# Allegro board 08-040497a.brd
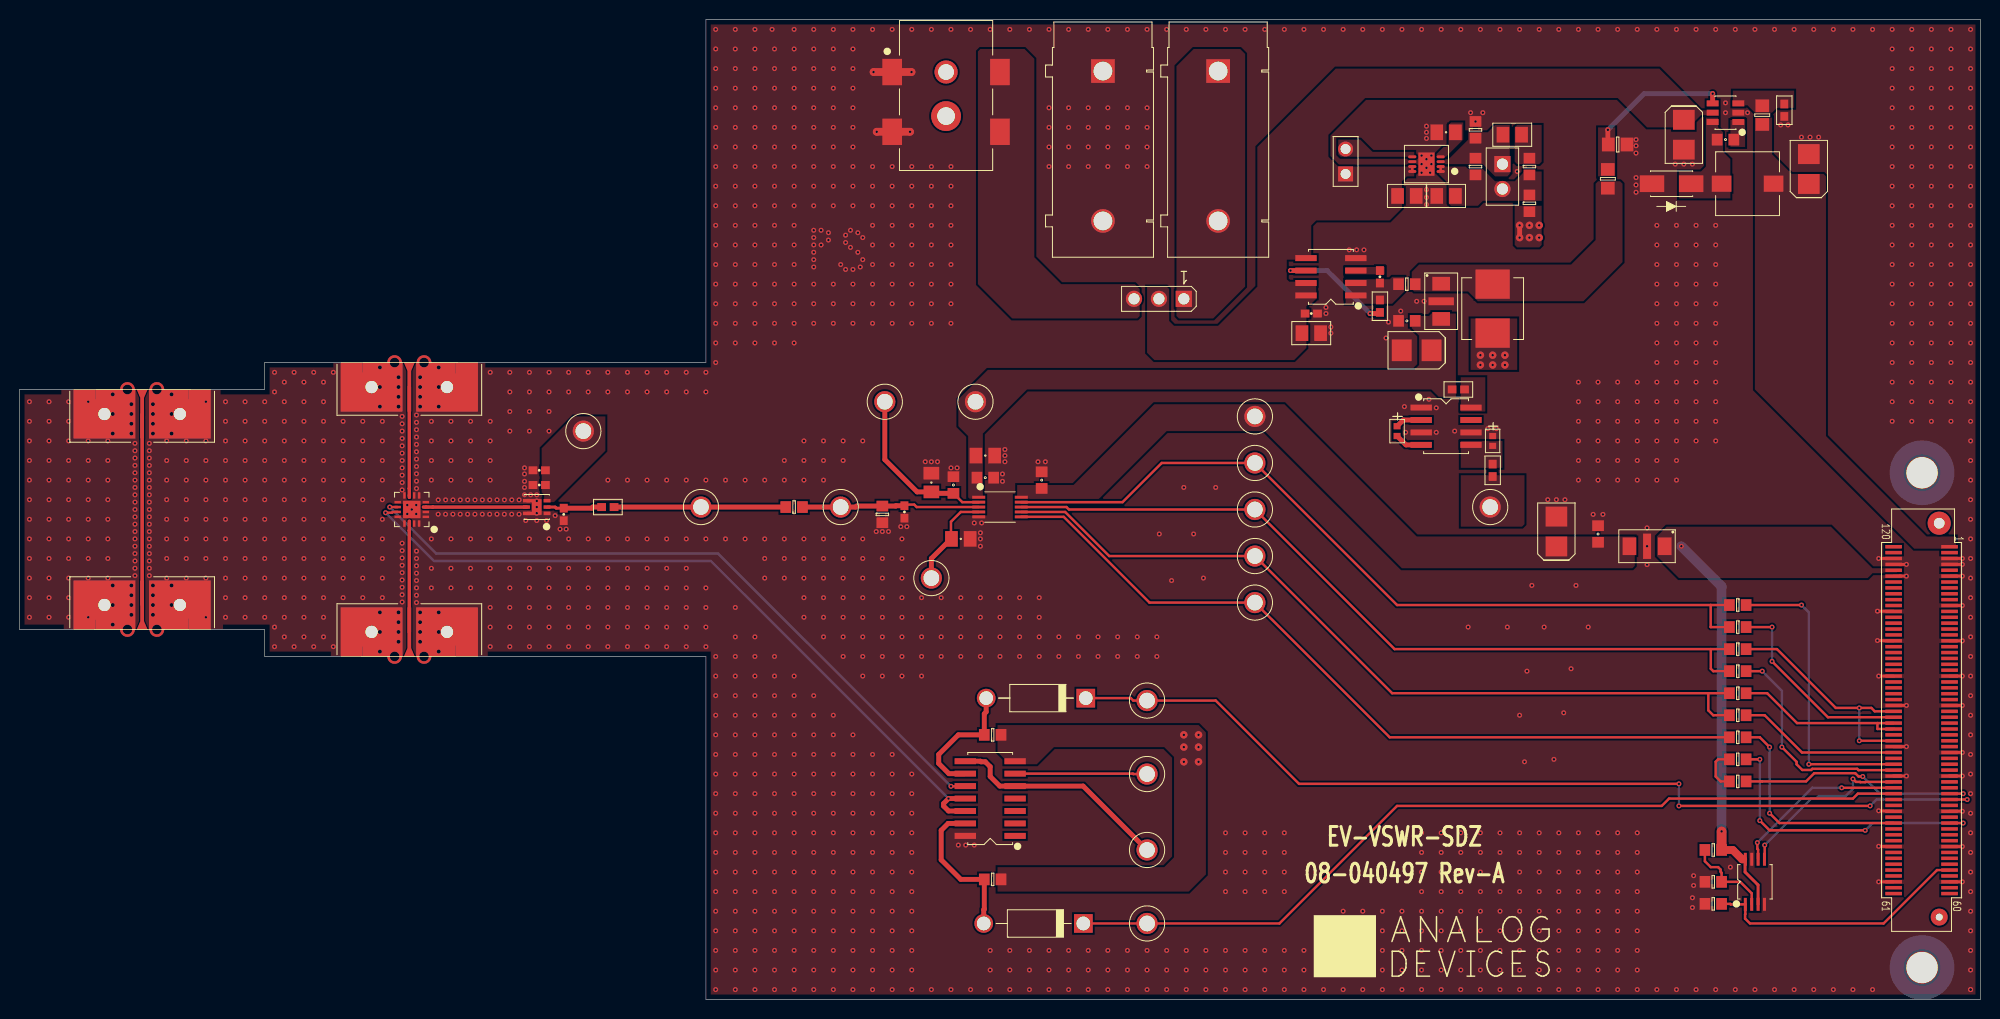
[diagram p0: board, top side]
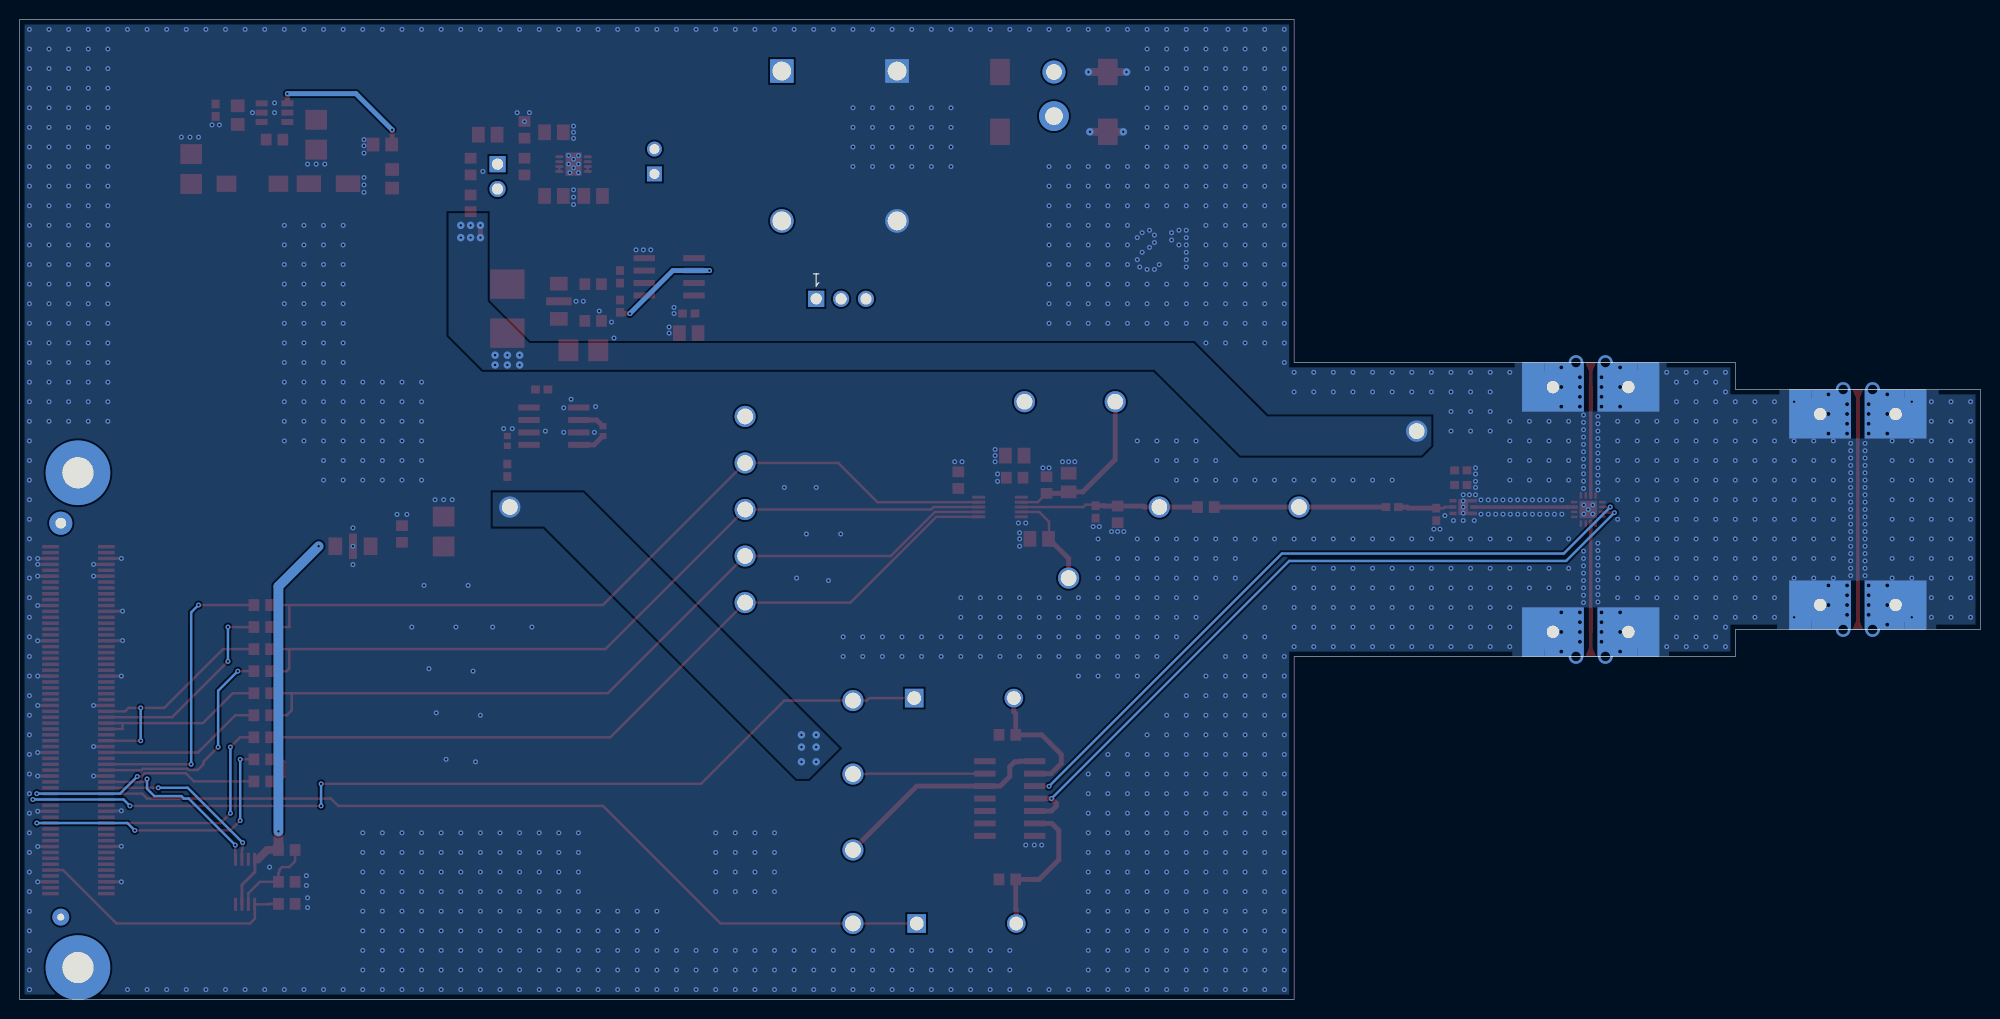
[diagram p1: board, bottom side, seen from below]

Outline 200 x 100 mm; copper layers: TOP, L2-GND, L3-GND, BOTTOM. Coordinates in mm from the lower left corner of the outline.
Outline path: 0,62.25 0,37.75 25,37.75 25,35 70,35 70,0 200,0 200,100 70,100 70,65 25,65 25,62.25 0,62.25

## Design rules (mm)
nets with their own width: min track width 0.3; nets AGND

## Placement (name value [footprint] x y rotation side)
A  WHT  [CNLOOPTP]  115 15.25 0 top
B  WHT  [CNLOOPTP]  115 23 0 top
C1  100pF  [C0402]  53 54 180 top
C2  0.1UF  [C0402]  53 52.5 180 top
C3  TBD0402  [C0402]  55.5 49.5 270 top
C9  1uF  [C0805]  98.5 55.5 0 top
C10  0.1uF  [C0603]  98.5 53.25 0 top
C11  0.1uF  [C0603]  95.25 52.5 90 top
C12  1uF  [C0805]  93 52.75 90 top
C14  1uF  [C0805]  96 47 0 top
C15  0.1uF  [C0603]  104.25 53 90 top
C17  0.01uF  [C0402]  131.75 70 0 top
C18  0.01UF  [C0402]  138.75 73.75 270 top
C19  0.1uF  [C0603]  141.5 69.25 180 top
C20  10uF  [C3528]  142.5 66.25 180 top
C21  10uF  [C3528]  169.75 88.25 270 top
C22  0.1uF  [C0603]  174 87.75 180 top
C23  10uF  [C3528]  182.5 84.75 90 top
C24  0.1uF  [C0603]  161 47.5 90 top
C25  10uF  [C3528]  156.75 47.75 90 top
C26  1UF  [C0805H53]  131.75 68 0 top
C29  1UF  [C0805H53]  152.25 88.25 0 top
C30  4.7UF  [C0805H53]  145.5 82 0 top
C31  1000pF  [C0805]  145.5 88.5 0 top
C32  4.7UF  [C0805H53]  141.5 82 180 top
C35  10uF  [CPL0402]  150.25 57 270 top
C36  10uF  [CPL0402]  140.5 58 270 top
C37  TBD0402  [C0402]  90.25 49.75 270 top
D1  B230A-13-F  [SMA-2]  168.5 83.25 180 top
D2  1N4733A  [DO41]  108.5 7.75 180 top
D3  1N4733A  [DO41]  108.75 30.75 180 top
GND  571-0100  [CNDELTRON-571]  110.5 94.75 270 top
GPIO1  WHT  [CNLOOPTP]  115 7.75 0 top
GPIO2  WHT  [CNLOOPTP]  115 30.5 0 top
J3  02K243-40M  [CNROS02K243-40M]  12.5 37.75 270 top
J4  FX8-120S-SV(21)  [CNHRSFX8-120S-SV_A]  194 28.5 270 top
J5  02K243-40M  [CNROS02K243-40M]  12.5 62.25 90 top
L1  6.8uH  [LSMSQ236H79_B]  176.25 83.25 0 top
L2  33uH  [L2525]  150.25 70.5 90 top
LC1  1000pF  [FLSML126W71H87]  145 71.25 270 top
LC2  1000pF  [FLSML126W71H87]  166 46.25 180 top
LK6  SAMTECTSW10608GS3PIN  [CNBERG1X3H205LD36]  118.75 71.5 180 top
LK21  M20-9990245  [CNHARWIN-M20-9990246]  151.25 85.25 270 top
LK22  69157-102  [CNBERG69157-102]  135.25 84.25 90 top
NOREF  -  []  0 37.75 90 top
NOREF#2  -  []  -153.6 -177.4 0 top
NOREF#3  -  []  245.81 331.87 0 top
NOREF#4  -  []  -153.6 -177.4 0 top
NOREF#5  -  []  200 0 90 top
NOREF#6  -  []  44.07 50.74 0 top
NOREF#7  -  []  0 62.25 0 top
NOREF#8  -  []  -133.3 -28.65 0 top
NOREF#9  -  []  -153.6 -177.4 0 top
NOREF#10  -  []  129.5 140.25 0 top
NOREF#11  -  []  40.89 52.79 0 top
NOREF#12  -  []  25 65 0 top
NOREF#13  -  []  40.54 48.23 0 top
NOREF#14  -  []  38.12 33.5 0 top
NOREF#15  -  []  70 100 0 top
NOREF#16  -  []  25 62.25 90 top
NOREF#17  -  []  41.3 51.3 0 top
NOREF#18  -  []  70 0 90 top
NOREF#19  -  []  39.11 52.78 0 top
NOREF#20  -  []  261.5 -98 0 top
NOREF#21  -  []  44.08 49.26 0 top
NOREF#22  -  []  25 35 90 top
NOREF#23  -  []  70 65 90 top
NOREF#24  -  []  132 2.25 180 bottom
R1  0  [R0402]  60 50.25 0 top
R12  330K  [R0402]  138.75 70.75 90 top
R13  3K  [R0805]  162 83.75 90 top
R14  1.5K  [R0805]  163 87.25 0 top
R15  53.6K  [R0805]  177.75 90.25 90 top
R16  10.2K  [R0402]  180 90.75 270 top
R17  TBD0603  [R0603]  175.25 33.5 180 top
R18  TBD0603  [R0603]  175.25 40.25 180 top
R19  TBD0603  [R0603]  175.25 29 180 top
R20  0  [R0603]  175.25 35.75 180 top
R21  0  [R0603]  175.25 31.25 180 top
R22  0  [R0603]  175.25 38 180 top
R23  0  [R0603]  175.25 24.5 0 top
R24  TBD0603  [R0603]  175.25 22.25 0 top
R25  TBD0603  [R0603]  175.25 26.75 180 top
R26  TBD0603  [R0603]  172.75 15.25 180 top
R27  100K  [R0603]  172.75 12 180 top
R28  100K  [R0603]  172.75 9.75 180 top
R30  10K  [R0603]  99.25 12.25 0 top
R31  200  [R0603]  79 50.25 0 top
R32  0  [R0603]  154 81.25 270 top
R33  3K  [R0603]  154 85 270 top
R34  120K  [R0603]  148.5 85 270 top
R35  39K  [R0603]  148.5 88.75 270 top
R36  10K  [R0603]  99.25 27 0 top
R37  0  [R0402]  146.75 62.25 180 top
R38  0  [R0402]  150.25 54 270 top
R39  0  [R0603]  141.5 73 0 top
R40  340  [R0603]  88 49.5 270 top
RF1  02K243-40M  [CNROS02K243-40M]  39.75 65 90 top
RF2  02K243-40M  [CNROS02K243-40M]  39.75 35 270 top
T1  WHT  [CNLOOPTP]  97.5 61 0 top
T2  WHT  [CNLOOPTP]  88.25 61 0 top
T3  WHT  [CNLOOPTP]  83.75 50.25 0 top
T4  WHT  [CNLOOPTP]  93 43 0 top
T6  WHT  [CNLOOPTP]  126 40.5 0 top
T7  WHT  [CNLOOPTP]  126 45.25 0 top
T8  WHT  [CNLOOPTP]  126 50 0 top
T9  WHT  [CNLOOPTP]  126 54.75 0 top
T10  WHT  [CNLOOPTP]  126 59.5 0 top
U1  ADL6010ACPZN  [UQFN6_2_05X2_05_PAD1_6X1_A]  52.75 50.25 90 top
U2  AD7091RBRMZ  [RM10]  100 50.25 270 top
U5  24LC32A-I/MS  [MSOP8]  177 12 0 top
U6  ADP3303ARZ-5  [SO8]  133.75 73.75 90 top
U7  ADP2301AUJZ  [TSOT23_6]  174 90.5 90 top
U8  ADM7170ACPZ  [DFN8_3X3_PAD2_38X1_64]  143.5 85.25 90 top
U9  74LV04AD  [SO14]  99 20.5 90 top
U10  -  [HMC547LP3E]  40 50 90 top
U11  ADM660ARZ  [SO8]  145.5 58.5 270 top
V_OUT  WHT  [CNLOOPTP]  69.5 50.25 0 top
VDET  RED  [CNLOOPTP]  57.5 58 0 top
VNEG  WHT  [CNLOOPTP]  150 50.25 0 top
VSUPPLY  KLDX-SMT2-0202-ATR  [CNKYCONKLDX-SMT2-0202]  94.5 92.25 270 top
VSUPPLY_ALT  571-0500  [CNDELTRON-571]  122.25 94.75 270 top

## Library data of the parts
A B GPIO1 GPIO2 T1-T4 T6-T10 V_OUT VNEG = CNTP1P: User Part Number: UPN; alternate symbols: (CNBANANA_ALT); part number: CNTP1P_TH-WHT,E000946,CNLOOPTP
C1 = CAP: Tolerance: 5; User Part Number: UPN; part number: CAP_SM-100PF,50V,5,E007896,C0402; tolerance: 5
C2 = CAP: Tolerance: 10; User Part Number: UPN; part number: CAP_SM-0.1UF,16V,10,E007200,C0402; tolerance: 10
C3 C37 = CAP: User Part Number: UPN; part number: CAP_SM-TBD0402,TBD0402,TBD0402,E000381,C0402
C9 C12 C14 = CAP: Tolerance: 10; User Part Number: UPN; part number: CAP_SM-1UF,100V,10,E014208,C0805; tolerance: 10
C10 C11 = CAP: Tolerance: 10; User Part Number: UPN; part number: CAP_SM-0.1UF,50V,10,E011865,C0603; tolerance: 10
C15 C19 C22 C24 = CAP: Tolerance: 10; User Part Number: UPN; part number: CAP_SM-0.1UF,50V,10,E015248,C0603; tolerance: 10
C17 = CAP: Tolerance: -0.25; User Part Number: UPN; part number: CAP_SM-0.01UF,50V,-0.25,E012614,C0402; tolerance: -0.25
C18 = CAP: Tolerance: 10; User Part Number: UPN; part number: CAP_SM-0.01UF,25V,10,E010983,C0402; tolerance: 10
C20 C21 C23 C25 = CAPP: User Part Number: UPN; Tolerance: 10; part number: CAPP_SM-10UF,20V,10,E011346,C3528; tolerance: 10
C26 C29 = CAP: Tolerance: 10; User Part Number: UPN; part number: CAP_SM-1UF,50V,10,E007202,C0805H53; tolerance: 10
C30 C32 = CAP: Tolerance: 10; User Part Number: UPN; part number: CAP_SM-4.7UF,25V,10,E006908,C0805H53; tolerance: 10
C31 = CAP: Tolerance: 5; User Part Number: UPN; part number: CAP_SM-1000PF,50V,5,E010100,C0805; tolerance: 5
C35 C36 = CAPP: User Part Number: UPN; Tolerance: 20; part number: CAPP_SM-10UF,6.3V,20,E022099,CPL0402; tolerance: 20
D1 = DIOSCHOTTKY: User Part Number: UPN; Tolerance: N/A; alternate symbols: (SOD882L_ALT); part number: DIOSCHOTTKY_SM-B230A-13-F,30V,N/A,E012952,SMA-2; tolerance: N/A
D2 D3 = DIOZNR: Tolerance: 5; User Part Number: UPN; part number: DIOZNR_TH-1N4733A,5.1V,5,E001229,DO41; tolerance: 5
GND = CN2P: User Part Number: UPN; part number: CN2P_TH-571-0100,E007691,CNDELTRON-571
J3 J5 RF1 RF2 = CNBNC3P: User Part Number: UPN; alternate symbols: (CNROS32K243-40ML5_ALT); part number: CNBNC3P_SM-02K243-40M,E010821,CNROS02K243-40M
J4 = CN120P_V4: User Part Number: UPN; part number: CN120P_V4_SM-FX8-120S-SV(21),E016993,CNHRSFX8-120S-SV_A
L1 = IND: Tolerance: 30; User Part Number: UPN; alternate symbols: (L0402-2,L0603_ALT,L1008L_ALT); part number: IND_SM-6.8UH,30,E021189,LSMSQ236H79_B; tolerance: 30
L2 = IND: Tolerance: 20; User Part Number: UPN; alternate symbols: (L0402-2,L0603_ALT,L1008L_ALT); part number: IND_SM-33UH,20,E002425,L2525; tolerance: 20
LC1 LC2 = FLTR3P_V3: User Part Number: UPN; part number: FLTR3P_V3_SM-1000PF,E019686,FLSML126W71H87
LK6 = CN3P: User Part Number: UPN; part number: CN3P_TH-SAMTECTSW10608GS3PIN,E000812,CNBERG1X3H205LD36
LK21 = CNJMPRSHRT: User Part Number: UPN; part number: CNJMPRSHRT_TH-M20-9990245,E019487,CNHARWIN-M20-9990246
LK22 = CNJMPRSHRT: User Part Number: UPN; part number: CNJMPRSHRT_TH-69157-102,E000942,CNBERG69157-102
R1 R37 R38 = RES: Tolerance: 5; User Part Number: UPN; part number: RES_SM-0,E003438,1/16W,5,R0402; tolerance: 5
R12 = RES: Tolerance: 5; User Part Number: UPN; part number: RES_SM-330K,E003461,1/16W,5,R0402; tolerance: 5
R13 = RES: Tolerance: 0.1; User Part Number: UPN; part number: RES_SM-3K,E013665,1/4W,0.1,R0805; tolerance: 0.1
R14 = RES: Tolerance: 0.1; User Part Number: UPN; part number: RES_SM-1.5K,E003822,1/10W,0.1,R0805; tolerance: 0.1
R15 = RES: Tolerance: 1; User Part Number: UPN; part number: RES_SM-53.6K,E003980,1/8W,1,R0805; tolerance: 1
R16 = RES: Tolerance: 1; User Part Number: UPN; part number: RES_SM-10.2K,E019451,1/16W,1,R0402; tolerance: 1
R17-R19 R24-R26 = RES: User Part Number: UPN; part number: RES_SM-TBD0603,E004050,TBD0603,TBD0603,R0603
R20-R23 R32 R39 = RES: Tolerance: 1; User Part Number: UPN; part number: RES_SM-0,E004207,1/16W,1,R0603; tolerance: 1
R27 R28 = RES: Tolerance: 1; User Part Number: UPN; part number: RES_SM-100K,E018430,1/16W,1,R0603; tolerance: 1
R30 R36 = RES: Tolerance: 0.1; User Part Number: UPN; part number: RES_SM-10K,E003965,1/10W,0.1,R0603; tolerance: 0.1
R31 = RES: Tolerance: 0.1; User Part Number: UPN; part number: RES_SM-200,E003955,1/10W,0.1,R0603; tolerance: 0.1
R33 = RES: Tolerance: 5; User Part Number: UPN; part number: RES_SM-3K,E003850,1/10W,5,R0603; tolerance: 5
R34 = RES: Tolerance: 1; User Part Number: UPN; part number: RES_SM-120K,E007774,0.1W,1,R0603; tolerance: 1
R35 = RES: Tolerance: 1; User Part Number: UPN; part number: RES_SM-39K,E004234,1/16W,1,R0603; tolerance: 1
R40 = RES: Tolerance: 1; User Part Number: UPN; part number: RES_SM-340,E012541,1/10W,1,R0603; tolerance: 1
U1 = ADL6010: User Part Number: UPN; alternate symbols: (UQFN6_2_05X2_05_PAD1_6X1); part number: ADL6010_SM-ADL6010ACPZN,E019839,UQFN6_2_05X2_05_PAD1_6X1_A
U2 = AD7091R_V2: User Part Number: UPN; part number: AD7091R_V2_SM-AD7091RBRMZ,E015495,RM10
U5 = IC24FC256: User Part Number: UPN; part number: IC24FC256_SM-24LC32A-I/MS,E014160,MSOP8
U6 = ADP3303: User Part Number: UPN; part number: ADP3303_SM-ADP3303ARZ-5,E004966,SO8
U7 = ADP2301: User Part Number: UPN; part number: ADP2301_SM-ADP2301AUJZ,E007310,TSOT23_6
U8 = ADM7170: User Part Number: UPN; part number: ADM7170_SM-ADM7170ACPZ,E020662,DFN8_3X3_PAD2_38X1_64
U9 = 7404: User Part Number: UPN; part number: 7404_SM-74LV04AD,E002109,SO14
U10 = ICHMC547LP3E: User Part Number: UPN; part number: ICHMC547LP3E_SM-HMC547LP3E,E011702,HMC547LP3E
U11 = ADM660: User Part Number: UPN; part number: ADM660_TH-ADM660ARZ,E006022,SO8
VDET = CNTP1P: User Part Number: UPN; alternate symbols: (CNBANANA_ALT); part number: CNTP1P_TH-RED,E000947,CNLOOPTP
VSUPPLY = CN4P_V2: User Part Number: UPN; part number: CN4P_V2_SM-KLDX-SMT2-0202-ATR,E015303,CNKYCONKLDX-SMT2-0202
VSUPPLY_ALT = CN2P: User Part Number: UPN; part number: CN2P_TH-571-0500,E007692,CNDELTRON-571

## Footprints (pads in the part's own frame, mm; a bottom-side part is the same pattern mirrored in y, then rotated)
C0402
  rect 0.889x0.813 smd: 1(-0.635,0) 2(0.635,0)
C0603
  rect 1.092x1.194 smd: 1(-0.851,0) 2(0.851,0)
C0805
  rect 1.295x1.6 smd: 1(-0.953,0) 2(0.953,0)
C0805H53
  rect 1.295x1.6 smd: 1(-0.953,0) 2(0.953,0)
C3528
  rect 2.032x2.21 smd: N(1.524,0) P(-1.524,0)
CNBERG1X3H205LD36
  rect 1.651x1.651 hole 1.143: 1(0,0)
  round 1.651 hole 1.143: 2(2.54,0) 3(5.08,0)
CNBERG69157-102
  rect 1.524x1.524 hole 1.016: 1(0,0)
  round 1.524 hole 1.016: 2(2.54,0)
CNDELTRON-571
  rect 2.413x2.413 hole 1.905: 1(0,0)
  round 2.413 hole 1.905: 2(15.3,0)
CNHARWIN-M20-9990246
  rect 1.651x1.651 hole 1.143: 1(0,0)
  round 1.651 hole 1.143: 2(2.54,0)
CNHRSFX8-120S-SV_A
  round 3.302 hole 3.175 unplated: (-25.25,0.05) (25.25,0.05)
  round 2.362 hole 1.092 unplated: (-20.1,1.8)
  round 1.727 hole 0.711 unplated: (20.1,1.8)
  rect 0.356x1.702 smd: 1(-17.7,2.851) 2(-17.1,2.851) 3(-16.5,2.851) 4(-15.9,2.851) 5(-15.3,2.851) 6(-14.7,2.851) 7(-14.1,2.851) 8(-13.5,2.851) 9(-12.9,2.851) 10(-12.3,2.851) 11(-11.7,2.851) 12(-11.1,2.851) 13(-10.5,2.851) 14(-9.9,2.851) 15(-9.3,2.851) 16(-8.7,2.851) 17(-8.1,2.851) 18(-7.5,2.851) 19(-6.9,2.851) 20(-6.3,2.851) 21(-5.7,2.851) 22(-5.1,2.851) 23(-4.5,2.851) 24(-3.9,2.851) 25(-3.3,2.851) 26(-2.7,2.851) 27(-2.1,2.851) 28(-1.5,2.851) 29(-0.9,2.851) 30(-0.3,2.851) 31(0.3,2.851) 32(0.9,2.851) 33(1.5,2.851) 34(2.1,2.851) 35(2.7,2.851) 36(3.3,2.851) 37(3.9,2.851) 38(4.5,2.851) 39(5.1,2.851) 40(5.7,2.851) 41(6.3,2.851) 42(6.9,2.851) 43(7.5,2.851) 44(8.1,2.851) 45(8.7,2.851) 46(9.3,2.851) 47(9.9,2.851) 48(10.5,2.851) 49(11.1,2.851) 50(11.7,2.851) 51(12.3,2.851) 52(12.9,2.851) 53(13.5,2.851) 54(14.1,2.851) 55(14.7,2.851) 56(15.3,2.851) 57(15.9,2.851) 58(16.5,2.851) 59(17.1,2.851) 60(17.7,2.851) 61(17.7,-2.851) 62(17.1,-2.851) 63(16.5,-2.851) 64(15.9,-2.851) 65(15.3,-2.851) 66(14.7,-2.851) 67(14.1,-2.851) 68(13.5,-2.851) 69(12.9,-2.851) 70(12.3,-2.851) 71(11.7,-2.851) 72(11.1,-2.851) 73(10.5,-2.851) 74(9.9,-2.851) 75(9.3,-2.851) 76(8.7,-2.851) 77(8.1,-2.851) 78(7.5,-2.851) 79(6.9,-2.851) 80(6.3,-2.851) 81(5.7,-2.851) 82(5.1,-2.851) 83(4.5,-2.851) 84(3.9,-2.851) 85(3.3,-2.851) 86(2.7,-2.851) 87(2.1,-2.851) 88(1.5,-2.851) 89(0.9,-2.851) 90(0.3,-2.851) 91(-0.3,-2.851) 92(-0.9,-2.851) 93(-1.5,-2.851) 94(-2.1,-2.851) 95(-2.7,-2.851) 96(-3.3,-2.851) 97(-3.9,-2.851) 98(-4.5,-2.851) 99(-5.1,-2.851) 100(-5.7,-2.851) 101(-6.3,-2.851) 102(-6.9,-2.851) 103(-7.5,-2.851) 104(-8.1,-2.851) 105(-8.7,-2.851) 106(-9.3,-2.851) 107(-9.9,-2.851) 108(-10.5,-2.851) 109(-11.1,-2.851) 110(-11.7,-2.851) 111(-12.3,-2.851) 112(-12.9,-2.851) 113(-13.5,-2.851) 114(-14.1,-2.851) 115(-14.7,-2.851) 116(-15.3,-2.851) 117(-15.9,-2.851) 118(-16.5,-2.851) 119(-17.1,-2.851) 120(-17.7,-2.851)
CNKYCONKLDX-SMT2-0202
  round 2.362 hole 1.6 unplated: (-2.4,0)
  round 3.048 hole 1.803 unplated: (2.1,0)
  rect 2.692x2.007 smd: 1(-2.4,-5.497) 2(3.7,-5.497) 3(3.7,5.497) 4(-2.4,5.497)
CNLOOPTP
  round 2.159 hole 1.6: 1(0,0)
CNROS02K243-40M
  custom 0.275x0.275 smd: 1(-2.5,0)
  custom 1.251x1.251 hole 2.108: 2(-2.508,3.848) 3(-2.508,-3.848)
CPL0402
  rect 0.635x0.711 smd: N(0.5,0) P(-0.5,0)
DFN8_3X3_PAD2_38X1_64
  oval 0.305x0.838 smd: 1(-0.75,-1.45) 2(-0.25,-1.45) 3(0.25,-1.45) 4(0.75,-1.45) 5(0.75,1.45) 6(0.25,1.45) 7(-0.25,1.45) 8(-0.75,1.45)
  rect 2.388x1.651 smd: PAD(0,0)
DO41
  round 1.905 hole 1.397: A(10.16,0)
  rect 1.905x1.905 hole 1.397: C(0,0)
FLSML126W71H87
  rect 1.397x1.803 smd: 1(-1.799,0) 3(1.799,0)
  rect 0.813x2.591 smd: 2(0,0)
HMC547LP3E
  rect 0.254x0.66 smd: 1(-0.751,-1.435) 2(-0.25,-1.435) 3(0.25,-1.435) 4(0.751,-1.435) 9(0.751,1.435) 10(0.25,1.435) 11(-0.25,1.435) 12(-0.751,1.435)
  rect 0.66x0.254 smd: 5(1.435,-0.751) 6(1.435,-0.25) 7(1.435,0.25) 8(1.435,0.751) 13(-1.435,0.751) 14(-1.435,0.25) 15(-1.435,-0.25) 16(-1.435,-0.751)
  rect 1.778x1.778 smd: PAD(0,0)
L2525
  rect 2.997x3.505 smd: 1(-2.502,0) 2(2.502,0)
LSMSQ236H79_B
  rect 2.007x1.651 smd: 1(-2.65,0) 2(2.65,0)
MSOP8
  rect 0.305x1.321 smd: 1(-0.975,-2.3) 2(-0.325,-2.3) 3(0.325,-2.3) 4(0.975,-2.3) 5(0.975,2.3) 6(0.325,2.3) 7(-0.325,2.3) 8(-0.975,2.3)
R0402
  rect 0.889x0.813 smd: 1(-0.635,0) 2(0.635,0)
R0603
  rect 1.092x1.194 smd: 1(-0.851,0) 2(0.851,0)
R0805
  rect 1.295x1.397 smd: 1(-0.953,0) 2(0.953,0)
RM10
  rect 0.305x1.321 smd: 1(-1,-2.171) 2(-0.5,-2.171) 3(0,-2.171) 4(0.5,-2.171) 5(1,-2.171) 6(1,2.171) 7(0.5,2.171) 8(0,2.171) 9(-0.5,2.171) 10(-1,2.171)
SMA-2
  rect 2.489x1.702 smd: A(1.995,0) C(-1.995,0)
SO8
  rect 0.61x2.184 smd: 1(-1.905,-2.54) 2(-0.635,-2.54) 3(0.635,-2.54) 4(1.905,-2.54) 5(1.905,2.54) 6(0.635,2.54) 7(-0.635,2.54) 8(-1.905,2.54)
SO14
  rect 0.61x2.184 smd: 1(-3.81,-2.54) 2(-2.54,-2.54) 3(-1.27,-2.54) 4(0,-2.54) 5(1.27,-2.54) 6(2.54,-2.54) 7(3.81,-2.54) 8(3.81,2.54) 9(2.54,2.54) 10(1.27,2.54) 11(0,2.54) 12(-1.27,2.54) 13(-2.54,2.54) 14(-3.81,2.54)
TSOT23_6
  rect 0.61x1.219 smd: 1(-0.95,-1.31) 2(0,-1.31) 3(0.95,-1.31) 4(0.95,1.31) 5(0,1.31) 6(-0.95,1.31)
UQFN6_2_05X2_05_PAD1_6X1_A
  rect 0.356x0.711 smd: 1(-0.65,-1.05) 2(0,-1.05) 3(0.65,-1.05) 4(0.65,1.05) 5(0,1.05) 6(-0.65,1.05)
  rect 1.6x0.991 smd: PAD(0,0)

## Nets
AGND: C1.2(N2) C2.2(N2) C3.2(N2) C9.2(N2) C10.2(N2) C11.2(N2) C12.2(N2) C14.2(N2) C15.2(N2) C17.2(N2) C19.2(N2) C20.N(N2) C21.N(N2) C23.N(N2) C24.2(N2) C25.N(N2) C26.2(N2) C30.1(N1) C31.1(N1) C32.1(N1) C35.P(N1) C37.2(N2) D1.A(P) GND.1(N1) GND.2(N2) J3.2(SH1) J3.3(SH2) J4.3(GND1) J4.4(GND2) J4.6(GND3) J4.11(GND4) J4.17(GND5) J4.23(GND6) J4.28(GND7) J4.36(GND8) J4.40(GND9) J4.46(GND10) J4.52(GND11) J4.58(GND12) J4.63(GND13) J4.69(GND14) J4.75(GND15) J4.81(GND16) J4.86(GND17) J4.93(GND18) J4.98(GND19) J4.104(GND20) J4.109(GND21) J4.115(GND22) J4.117(GND23) J4.118(GND24) J5.2(SH1) J5.3(SH2) LC1.2(C) LC2.2(C) R14.2(N2) R16.2(N2) R27.2(N2) R28.2(N2) R35.1(N1) R40.2(N2) RF1.2(SH1) RF1.3(SH2) RF2.2(SH1) RF2.3(SH2) U1.1(GND1) U1.4(GND2) U1.6(GND3) U1.PAD U2.5(GND) U5.4(VSS) U5.7(WP) U6.4(GND) U7.2(GND) U8.6(GND) U8.PAD(EP) U9.14(VDD) U10.1(NC1) U10.2(GND1) U10.4(GND2) U10.5(NC2) U10.6(GND3) U10.8(GND4) U10.9(NC3) U10.12(NC4) U10.13(GND5) U10.15(GND6) U10.16(NC5) U10.PAD U11.1(FC) U11.3(GND) U11.6(LV) VSUPPLY.1(N1) VSUPPLY.2(N2)
AVDD: C9.1(N1) C10.1(N1) C19.1(N1) C20.P(N1) LC1.3(L2) R37.2(N2) T1.1(N1) U2.1(VDD)
A: A.1(N1) U9.5(IN) U9.8(OUT_N)
B: B.1(N1) U9.6(OUT_N)
CONVST: R23.1(N1) R24.1(N1)
CONVSTB: R25.2(N2) T6.1(N1) U2.6(CONVST_N)
CSB: R19.2(N2) R21.2(N2) T7.1(N1) U2.7(CS_N)
GPIO1: D2.C(N) GPIO1.1(N1) J4.78(GPIO1)
GPIO2: D3.C(N) GPIO2.1(N1) J4.44(GPIO2)
RF1: RF1.1(CNTR) U10.7(RF1)
RF2: RF2.1(CNTR) U10.14(RF2)
RF_TRUE_CAL: J3.1(CNTR) J5.1(CNTR)
RFIN: U1.5(RFIN) U10.3(RFC)
SCLK: R17.2(N2) R20.2(N2) T8.1(N1) U2.8(SCLK)
SDO: R18.2(N2) R22.2(N2) T9.1(N1) U2.9(SDO)
UNNAMED_3_AD7091RV2_I14_REFOUT: C11.1(N1) C12.1(N1) T2.1(N1) U2.2(REFOUT)
UNNAMED_3_AD7091RV2_I14_VIN: C37.1(N1) R31.2(N2) R40.1(N1) T3.1(N1) U2.3(VIN)
UNNAMED_3_CAP_I29_N1: C14.1(N1) T4.1(N1) U2.4(REGCAP)
UNNAMED_4_ADM660_I4_CAP: C36.N(N2) U11.4(CAP-)
UNNAMED_4_ADM660_I4_CAP_1: C36.P(N1) U11.2(CAP+)
UNNAMED_4_ADM660_I4_OUT: C35.N(N2) R38.1(N1) U11.5(OUT)
UNNAMED_4_ADM660_I4_V: R37.1(N1) U11.8(V+)
UNNAMED_4_ADM7170_I67_EN: LK22.2(S2) U8.5(EN)
UNNAMED_4_ADM7170_I67_SENSE: C29.1(N1) LK21.1(S1) R34.1(N1) R35.2(N2) U8.3(SENSE)
UNNAMED_4_ADM7170_I67_SS: C31.2(N2) U8.4(SS)
UNNAMED_4_ADM7170_I67_VOUT1: C30.2(N2) LK21.2(S2) R32.1(N1) R33.2(N2) R34.2(N2) U8.1(VOUT1) U8.2(VOUT2)
UNNAMED_4_ADP2301_I57_BST: C22.1(N1) U7.1(BST)
UNNAMED_4_ADP2301_I57_EN: R13.2(N2) R14.1(N1) U7.4(EN)
UNNAMED_4_ADP2301_I57_FB: R15.2(N2) R16.1(N1) U7.3(FB)
UNNAMED_4_ADP2301_I57_SW: C22.2(N2) D1.C(N) L1.1(N1) U7.6(SW)
UNNAMED_4_ADP3303_I47_ERRN: R12.1(N1) U6.6(ERR_N)
UNNAMED_4_ADP3303_I47_NR: C18.1(N1) U6.3(NR)
UNNAMED_4_ADP3303_I47_OUT: C18.2(N2) R12.2(N2) R39.1(N1) U6.1(OUT) U6.2(OUT1)
UNNAMED_4_CAP_I91_N2: C29.2(N2) R33.1(N1)
UNNAMED_4_CN2P_I42_N1: LK6.1(N1) VSUPPLY_ALT.1(N1) VSUPPLY_ALT.2(N2)
UNNAMED_4_CN4PV2_I45_N3: LK6.3(N3) VSUPPLY.3(N3) VSUPPLY.4(N4)
UNNAMED_5_CN120PV4_I55_EEPROMA0: J4.56(EEPROM_A0) R28.1(N1) U5.1(A0)
UNNAMED_5_CN120PV4_I55_GPIO0: J4.43(GPIO0) R24.2(N2)
UNNAMED_5_CN120PV4_I55_SCL0: J4.79(SCL_0) U5.6(SCL)
UNNAMED_5_CN120PV4_I55_SDA0: J4.80(SDA_0) U5.5(SDA)
UNNAMED_5_CN120PV4_I55_SPICLK: J4.82(SPI_CLK) R17.1(N1)
UNNAMED_5_CN120PV4_I55_SPIMISO: J4.83(SPI_MISO) R18.1(N1)
UNNAMED_5_CN120PV4_I55_SPISELA: J4.85(SPI_SEL_A) R19.1(N1)
UNNAMED_5_CN120PV4_I55_SPORTDR0: J4.91(SPORT_DR0) R22.1(N1)
UNNAMED_5_CN120PV4_I55_SPORTRFS: J4.89(SPORT_TFS) J4.90(SPORT_RFS) R21.1(N1)
UNNAMED_5_CN120PV4_I55_SPORTRSC: J4.87(SPORT_TSCLK) J4.92(SPORT_RSCLK) R20.1(N1)
UNNAMED_5_CN120PV4_I55_TMRA: J4.48(TMR_A) R23.2(N2)
UNNAMED_5_CN120PV4_I55_TMRB: J4.73(TMR_B) R25.1(N1)
UNNAMED_5_IC24FC256_I33_A1: R26.2(N2) R27.1(N1) U5.2(A1)
UNNAMED_8_7404_I38_IN: U9.11(IN) U9.12(OUT_N) U10.11(A)
UNNAMED_8_7404_I38_OUTN: U9.10(OUT_N) U10.10(B)
UNNAMED_8_7404_I39_IN: D2.A(P) R30.1(N1) U9.13(IN)
UNNAMED_8_7404_I65_IN: D3.A(P) R36.1(N1) U9.9(IN)
UNNAMED_8_ADL6010_I98_VOUT: C3.1(N1) R1.1(N1) U1.2(VOUT)
V_IN: C17.1(N1) C21.P(N1) C26.1(N1) C32.2(N2) LK6.2(N2) LK22.1(S1) U6.5(SD_N) U6.7(IN) U6.8(IN1) U7.5(VIN) U8.7(VIN2) U8.8(VIN1)
V_OUT: R1.2(N2) R31.1(N1) V_OUT.1(N1)
VDET: C1.1(N1) C2.1(N1) L2.1(N1) R32.2(N2) U1.3(VPOS) VDET.1(N1)
VDRIVE: C15.1(N1) C24.1(N1) C25.P(N1) LC2.3(L2) T10.1(N1) U2.10(VDRIVE)
VIO_CONNECTOR: J4.116(VIO(+3.3V)) LC2.1(L1) R26.1(N1) U5.3(A2) U5.8(VCC)
VNEG: R30.2(N2) R36.2(N2) R38.2(N2) U9.7(VSS) VNEG.1(N1)
VSDP: C23.P(N1) J4.1(VIN) L1.2(N2) R15.1(N1)
VSDP_EN: L2.2(N2) LC1.1(L1) R13.1(N1) R39.2(N2)

Pads without a net: J4 2 5 7 8 9 10 12 13 14 15 16 18 19 20 21 22 24 25 26 27 29 30 31 32 33 34 35 37 38 39 41 42 45 47 49 50 51 53 54 55 57 59 60 61 62 64 65 66 67 68 70 71 72 74 76 77 84 88 94 95 96 97 99 100 101 102 103 105 106 107 108 110 111 112 113 114 119 120; U9 1 2 3 4; U11 7

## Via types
v1: diameter 0.762, hole 0.254, TOP to BOTTOM, 22 vias
v2: diameter 0.508, hole 0.254, TOP to BOTTOM, 1593 vias
v3: diameter 0.66, hole 0.406, TOP to BOTTOM, 55 vias
v4: diameter 1.499, hole 0.991, TOP to BOTTOM, 8 vias

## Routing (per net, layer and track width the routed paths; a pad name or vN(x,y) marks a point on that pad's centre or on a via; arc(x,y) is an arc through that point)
AGND: length 40.4
  TOP w0.3: J4.63 v2(189.62,12) ; J4.58 v2(198.16,12) ; J4.11 v2(198.16,40.2) ; J4.117 v2(192.45,44.4) ; J4.104 v2(189.5,36.62) ; J4.109 v2(189.5,39.62) ; J4.4 v2(198.16,44.4) ; J4.3 v2(198.16,45) ; J4.52 v2(198.16,15.6) ; J4.28 v2(198.16,30) ; J4.23 v2(198.16,33) ; J4.98 v2(189.62,33) ; J4.46 v2(198.16,19.2) ; J4.93 v2(192.45,30) ; J4.81 v2(192.45,22.8) ; J4.17 v2(198.16,36.6) ; J4.86 v2(192.45,25.8) ; J4.36 v2(198.16,25.2) ; J4.69 v2(189.62,15.62) ; J4.40 v2(198.16,22.8) ; J4.118 v2(189.62,45) ; J4.115 v2(192.45,43.2) ; J4.6 v2(198.16,43.2) ; J4.75 v2(189.62,19.25)
  TOP w0.8: v1(90.83,88.55) VSUPPLY.2 v1(87.42,88.55) ; v1(90.97,94.65) VSUPPLY.1 v1(87.1,94.65)
  vias: v2(1,61) v2(1,59) v2(1,57) v2(1,55) v2(1,53) v2(1,51) v2(1,49) v2(1,47) v2(1,45) v2(1,43) v2(1,41) v2(1,39) v2(3,61) v2(3,59) v2(3,57) v2(3,55) v2(3,53) v2(3,51) v2(3,49) v2(3,47) v2(3,45) v2(3,43) v2(3,41) v2(3,39) v2(5,61) v2(5,59) v2(5,57) v2(5,55) v2(5,53) v2(5,51) v2(5,49) v2(5,47) v2(5,45) v2(5,43) v2(5,41) v2(5,39) v2(7,61) v2(7,57) v2(7,55) v2(7,53) v2(7,51) v2(7,49) v2(7,47) v2(7,45) v2(7,43) v2(7,39) v2(9,57) v2(9,55) v2(9,53) v2(9,51) v2(9,49) v2(9,47) v2(9,45) v2(9,43) v2(11.77,56.75) v2(11.77,56) v2(11.77,55.25) v2(11.77,54.5) v2(11.77,53.75) v2(11.77,53) v2(11.77,52.25) v2(11.77,51.5) v2(11.77,50.75) v2(11.77,50) v2(11.77,49.25) v2(11.77,48.5) v2(11.77,47.75) v2(11.77,47) v2(11.77,46.25) v2(11.77,45.5) v2(11.77,44.75) v2(11.77,44) v2(11.77,43.25) v2(13.23,56.75) v2(13.23,56) v2(13.23,55.25) v2(13.23,54.5) v2(13.23,53.75) v2(13.23,53) v2(13.23,52.25) v2(13.23,51.5) v2(13.23,50.75) v2(13.23,50) v2(13.23,49.25) v2(13.23,48.5) v2(13.23,47.75) v2(13.23,47) v2(13.23,46.25) v2(13.23,45.5) v2(13.23,44.75) v2(13.23,44) v2(13.23,43.25) v2(15,57) v2(15,55) v2(15,53) v2(15,51) v2(15,49) v2(15,47) v2(15,45) v2(15,43) v2(17,57) v2(17,55) v2(17,53) v2(17,51) v2(17,49) v2(17,47) v2(17,45) v2(17,43) v2(19,61) v2(19,57) v2(19,55) v2(19,53) v2(19,51) v2(19,49) v2(19,47) v2(19,45) v2(19,43) v2(19,39) v2(21,61) v2(21,59) v2(21,57) v2(21,55) v2(21,53) v2(21,51) v2(21,49) v2(21,47) v2(21,45) v2(21,43) v2(21,41) v2(21,39) v2(23,61) v2(23,59) v2(23,57) v2(23,55) v2(23,53) v2(23,51) v2(23,49) v2(23,47) v2(23,45) v2(23,43) v2(23,41) v2(23,39) v2(25,61) v2(25,59) v2(25,57) v2(25,55) v2(25,53) v2(25,51) v2(25,49) v2(25,47) v2(25,45) v2(25,43) v2(25,41) v2(25,39) v2(26,64) v2(26,62) v2(26,38) v2(26,36) v2(27,63) v2(27,61) v2(27,59) v2(27,57) v2(27,55) v2(27,53) v2(27,51) v2(27,49) v2(27,47) v2(27,45) v2(27,43) v2(27,41) v2(27,39) v2(27,37) v2(28,64) v2(28,36) v2(29,63) v2(29,61) v2(29,59) v2(29,57) v2(29,55) v2(29,53) v2(29,51) v2(29,49) v2(29,47) v2(29,45) v2(29,43) v2(29,41) v2(29,39) v2(29,37) v2(30,64) v2(30,36) v2(31,63) v2(31,61) v2(31,59) v2(31,57) v2(31,55) v2(31,53) v2(31,51) v2(31,49) v2(31,47) v2(31,45) v2(31,43) v2(31,41) v2(31,39) v2(31,37) v2(32,64) v2(32,36) v2(33,59) v2(33,57) v2(33,55) v2(33,53) v2(33,51) v2(33,49) v2(33,47) v2(33,45) v2(33,43) v2(33,41) v2(35,59) v2(35,57) v2(35,55) v2(35,53) v2(35,51) v2(35,49) v2(35,47) v2(35,45) v2(35,43) v2(35,41) v2(35.9,62.49) v2(37,59) v2(37,57) v2(37,55) v2(37,53) v2(37,51) v2(37,49) v2(37,47) v2(37,45) v2(37,43) v2(37,41) v2(39.02,59.5) v2(39.02,58.75) v2(39.02,58) v2(39.02,57.25) v2(39.02,56.5) v2(39.02,55.75) v2(39.02,55) v2(39.02,54.25) v2(39.02,53.5) v2(39.02,52.75) v2(39.02,52) v2(39.02,46.56) v2(39.02,45.81) v2(39.02,45.06) v2(39.02,44.31) v2(39.02,43.56) v2(39.02,42.81) v2(39.02,42.06) v2(39.02,41.31) v2(39.02,40.56) v2(39.54,50.46) v2(39.54,49.54) v2(40,50) v2(40.48,59.64) v2(40.48,58.89) v2(40.48,58.14) v2(40.48,57.39) v2(40.48,56.64) v2(40.48,55.89) v2(40.48,55.14) v2(40.48,54.39) v2(40.48,53.64) v2(40.48,52.89) v2(40.48,52.14) v2(40.46,50.46) v2(40.46,49.54) v2(40.48,45.75) v2(40.48,45) v2(40.48,44.25) v2(40.48,43.5) v2(40.48,42.75) v2(40.48,42) v2(40.48,41.25) v2(40.48,40.5) v2(42,59) v2(42,57) v2(42,55) v2(42,53) v2(42,47) v2(42,44) v2(42,42) v2(42.7,50.98) v2(42.69,49.52) v2(43.45,50.98) v2(43.44,49.52) v2(43.6,62.49) v2(44,59) v2(44,57) v2(44,55) v2(44,53) v2(44,47) v2(44,44) v2(44,42) v2(44.2,50.98) v2(44.19,49.52) v2(44.95,50.98) v2(44.94,49.52) v2(45.7,50.98) v2(45.69,49.52) v2(46,59) v2(46,57) v2(46,55) v2(46,53) v2(46,47) v2(46,44) v2(46,42) v2(46.45,50.98) v2(46.44,49.52) v2(47.2,50.98) v2(47.19,49.52) v2(47.95,50.98) v2(47.94,49.52) v2(48,64) v2(48,59) v2(48,57) v2(48,55) v2(48,53) v2(48,47) v2(48,44) v2(48,42) v2(48,40) v2(48,38) v2(48,36) v2(48.7,50.98) v2(48.69,49.52) v2(49.45,50.98) v2(49.44,49.52) v2(50,64) v2(50,62) v2(50,60) v2(50,58) v2(50,47) v2(50,44) v2(50,42) v2(50,40) v2(50,38) v2(50,36) v2(50.2,50.98) v2(50.19,49.52) v2(50.95,50.98) v2(50.94,49.52) v2(51.5,54.25) v2(51.5,53.62) v2(51.5,52.88) v2(51.5,52.25) v2(51.5,51.5) v2(51.62,48.88) v2(52,64) v2(52,62) v2(52,60) v2(52,58) v2(52,47) v2(52,44) v2(52,42) v2(52,40) v2(52,38) v2(52,36) v2(52.12,51.5) v2(52.75,51.5) v2(52.75,50.88) v2(52.75,50.25) v2(52.75,49.62) v2(52.75,48.88) v2(53.75,48.88) v2(54,64) v2(54,62) v2(54,60) v2(54,58) v2(54,47) v2(54,44) v2(54,42) v2(54,40) v2(54,38) v2(54,36) v2(54.62,49.38) v2(55.12,48) v2(55.75,48) v2(56,64) v2(56,62) v2(56,47) v2(56,44) v2(56,42) v2(56,40) v2(56,38) v2(56,36) v2(58,64) v2(58,62) v2(58,47) v2(58,44) v2(58,42) v2(58,40) v2(58,38) v2(58,36) v2(60,64) v2(60,62) v2(60,53) v2(60,47) v2(60,44) v2(60,42) v2(60,40) v2(60,38) v2(60,36) v2(62,64) v2(62,62) v2(62,53) v2(62,47) v2(62,44) v2(62,42) v2(62,40) v2(62,38) v2(62,36) v2(64,64) v2(64,62) v2(64,53) v2(64,47) v2(64,44) v2(64,42) v2(64,40) v2(64,38) v2(64,36) v2(66,64) v2(66,62) v2(66,53) v2(66,47) v2(66,44) v2(66,42) v2(66,40) v2(66,38) v2(66,36) v2(68,64) v2(68,62) v2(68,53) v2(68,47) v2(68,44) v2(68,42) v2(68,40) v2(68,38) v2(68,36) v2(70,64) v2(70,62) v2(70,53) v2(70,47) v2(70,42) v2(70,40) v2(70,38) v2(70,36) v2(71,99) v2(71,97) v2(71,95) v2(71,93) v2(71,91) v2(71,89) v2(71,87) v2(71,85) v2(71,83) v2(71,81) v2(71,79) v2(71,77) v2(71,75) v2(71,73) v2(71,71) v2(71,69) v2(71,67) v2(71,65) v2(71,35) v2(71,33) v2(71,31) v2(71,29) v2(71,27) v2(71,25) v2(71,23) v2(71,21) v2(71,19) v2(71,17) v2(71,15) v2(71,13) v2(71,11) v2(71,9) v2(71,7) v2(71,5) v2(71,3) v2(71,1) v2(72,53) v2(72,47) v2(73,99) v2(73,97) v2(73,95) v2(73,93) v2(73,91) v2(73,89) v2(73,87) v2(73,85) v2(73,83) v2(73,81) v2(73,79) v2(73,77) v2(73,75) v2(73,73) v2(73,71) v2(73,69) v2(73,67) v2(73,40) v2(73,37) v2(73,35) v2(73,33) v2(73,31) v2(73,29) v2(73,27) v2(73,25) v2(73,23) v2(73,21) v2(73,19) v2(73,17) v2(73,15) v2(73,13) v2(73,11) v2(73,9) v2(73,7) v2(73,5) v2(73,3) v2(73,1) v2(74,53) v2(74,47) v2(75,99) v2(75,97) v2(75,95) v2(75,93) v2(75,91) v2(75,89) v2(75,87) v2(75,85) v2(75,83) v2(75,81) v2(75,79) v2(75,77) v2(75,75) v2(75,73) v2(75,71) v2(75,69) v2(75,67) v2(75,37) v2(75,35) v2(75,33) v2(75,31) v2(75,29) v2(75,27) v2(75,25) v2(75,23) v2(75,21) v2(75,19) v2(75,17) v2(75,15) v2(75,13) v2(75,11) v2(75,9) v2(75,7) v2(75,5) v2(75,3) v2(75,1) v2(76,53) v2(76,47) v2(76,45) v2(76,43) v2(76.75,99) v2(77,97) v2(77,95) v2(77,93) v2(77,91) v2(77,89) v2(77,87) v2(77,85) v2(77,83) v2(77,81) v2(77,79) v2(77,77) v2(77,75) v2(77,73) v2(77,71) v2(77,69) v2(77,67) v2(77,35) v2(77,33) v2(77,31) v2(77,29) v2(77,27) v2(77,25) v2(77,23) v2(77,21) v2(77,19) v2(77,17) v2(77,15) v2(77,13) v2(77,11) v2(77,9) v2(77,7) v2(77,5) v2(77,3) v2(77,1) v2(78,55) v2(78,53) v2(78,47) v2(78,45) v2(78,43) v2(79,99) v2(79,97) v2(79,95) v2(79,93) v2(79,91) v2(79,89) v2(79,87) v2(79,85) v2(79,83) v2(79,81) v2(79,79) v2(79,77) v2(79,75) v2(79,73) v2(79,71) v2(79,69) v2(79,67) v2(79,33) v2(79,31) v2(79,29) v2(79,27) v2(79,25) v2(79,23) v2(79,21) v2(79,19) v2(79,17) v2(79,15) v2(79,13) v2(79,11) v2(79,9) v2(79,7) v2(79,5) v2(79,3) v2(79,1) v2(80,57) v2(80,55) v2(80,53) v2(80,47) v2(80,45) v2(80,43) v2(80,41) v2(80,39) v2(81,99) v2(81,97) v2(81,95) v2(81,93) v2(81,91) v2(81,89) v2(81,87) v2(81,85) v2(81,83) v2(81,81) v2(81,78.5) v2(81,77.75) v2(81,77) v2(81,76.25) v2(81,75.5) v2(81,74.75) v2(81,73) v2(81,71) v2(81,69) v2(81,31) v2(81,29) v2(81,27) v2(81,25) v2(81,23) v2(81,21) v2(81,19) v2(81,17) v2(81,15) v2(81,13) v2(81,11) v2(81,9) v2(81,7) v2(81,5) v2(81,3) v2(81,1) v2(81.75,78.5) v2(81.75,77) v2(82,57) v2(82,55) v2(82,53) v2(82,47) v2(82,45) v2(82,43) v2(82,41) v2(82,39) v2(82,37) v2(82.5,78.25) v2(82.5,77.5) v2(83,99) v2(83,97) v2(83,95) v2(83,93) v2(83,91) v2(83,89) v2(83,87) v2(83,85) v2(83,83) v2(83,81) v2(83,73) v2(83,71) v2(83,69) v2(83,29) v2(83,27) v2(83,25) v2(83,23) v2(83,21) v2(83,19) v2(83,17) v2(83,15) v2(83,13) v2(83,11) v2(83,9) v2(83,7) v2(83,5) v2(83,3) v2(83,1) v2(83.75,75) v2(84,57) v2(84,55) v2(84,47) v2(84,45) v2(84,43) v2(84,41) v2(84,39) v2(84,37) v2(84,35) v2(84.25,78) v2(84.25,77.25) v2(84.25,74.5) v2(84.75,78.5) v2(84.75,76.75) v2(85,99) v2(85,97) v2(85,95) v2(85,93) v2(85,91) v2(85,89) v2(85,87) v2(85,85) v2(85,83) v2(85,81) v2(85,74.5) v2(85,73) v2(85,71) v2(85,69) v2(85,27) v2(85,25) v2(85,23) v2(85,21) v2(85,19) v2(85,17) v2(85,15) v2(85,13) v2(85,11) v2(85,9) v2(85,7) v2(85,5) v2(85,3) v2(85,1) v2(85.5,78.25) v2(85.5,76.25) v2(85.75,74.75) v2(86,77.75) v2(86,75.5) v2(86,57) v2(86,47) v2(86,45) v2(86,43) v2(86,41) v2(86,39) v2(86,37) v2(86,35) v2(86,33) v2(87,99) v2(87,85) v2(87,83) v2(87,81) v2(87,79) v2(87,77) v2(87,75) v2(87,73) v2(87,71) v2(87,69) v2(87,25) v2(87,23) v2(87,21) v2(87,19) v2(87,17) v2(87,15) v2(87,13) v2(87,11) v2(87,9) v2(87,7) v2(87,5) v2(87,3) v2(87,1) v2(87.38,47.75) v2(88,47.75) v2(88,45) v2(88,43) v2(88,41) v2(88,39) v2(88,37) v2(88,35) v2(88,33) v2(88.62,47.75) v2(89,99) v2(89,85) v2(89,83) v2(89,81) v2(89,79) v2(89,77) v2(89,75) v2(89,73) v2(89,71) v2(89,69) v2(89,25) v2(89,23) v2(89,21) v2(89,19) v2(89,17) v2(89,15) v2(89,13) v2(89,11) v2(89,9) v2(89,7) v2(89,5) v2(89,3) v2(89,1) v2(89.88,48.25) v2(90,47) v2(90,45) v2(90,43) v2(90,41) v2(90,39) v2(90,37) v2(90,35) v2(90,33) v2(90.5,48.25) v2(91,99) v2(91,85) v2(91,83) v2(91,81) v2(91,79) v2(91,77) v2(91,75) v2(91,73) v2(91,71) v2(91,69) v2(91,23) v2(91,21) v2(91,19) v2(91,17) v2(91,15) v2(91,13) v2(91,11) v2(91,9) v2(91,7) v2(91,5) v2(91,3) v2(91,1) v2(92,41) v2(92,39) v2(92,37) v2(92,35) v2(92,33) v2(92.38,54.88) v2(93,99) v2(93,85) v2(93,83) v2(93,81) v2(93,79) v2(93,77) v2(93,75) v2(93,73) v2(93,71) v2(93,69) v2(93,54.88) v2(93,1) v2(93.62,54.88) v2(94,41) v2(94,39) v2(94,37) v2(94,35) v2(95,99) v2(95,85) v2(95,83) v2(95,81) v2(95,79) v2(95,77) v2(95,75) v2(95,73) v2(95,71) v2(95,69) v2(95,54.25) v2(95,1) v2(95.62,54.25) v2(95.75,15.75) v2(96,41) v2(96,39) v2(96,37) v2(96,35) v2(96.5,15.75) v2(97,99) v2(97,1) v2(97.38,48.62) v2(97.38,15.75) v2(98,47.62) v2(98,47) v2(98,46.25) v2(98,41) v2(98,39) v2(98,37) v2(98,35) v2(98.12,48.62) v2(99,99) v2(99,5) v2(99,3) v2(99,1) v2(100,41) v2(100,39) v2(100,37) v2(100,35) v2(100.25,53.62) v2(100.25,52.88) v2(100.5,56.12) v2(100.5,55.5) v2(100.5,54.88) v2(101,99) v2(101,5) v2(101,3) v2(101,1) v2(102,41) v2(102,39) v2(102,37) v2(102,35) v2(103,99) v2(103,5) v2(103,3) v2(103,1) v2(103.88,54.88) v2(104,41) v2(104,39) v2(104,37) v2(104,35) v2(104.62,54.88) v2(105,99) v2(105,91) v2(105,89) v2(105,87) v2(105,85) v2(105,5) v2(105,3) v2(105,1) v2(106,37) v2(106,35) v2(107,99) v2(107,91) v2(107,89) v2(107,87) v2(107,85) v2(107,5) v2(107,3) v2(107,1) v2(108,37) v2(108,35) v2(109,99) v2(109,91) v2(109,89) v2(109,87) v2(109,85) v2(109,5) v2(109,3) v2(109,1) v2(110,37) v2(110,35) v2(111,99) v2(111,91) v2(111,89) v2(111,87) v2(111,85) v2(111,5) v2(111,3) v2(111,1) v2(112,37) v2(112,35) v2(113,99) v2(113,91) v2(113,89) v2(113,87) v2(113,85) v2(113,5) v2(113,3) v2(113,1) v2(114,37) v2(114,35) v2(115,99) v2(115,91) v2(115,89) v2(115,87) v2(115,85) v2(115,5) v2(115,3) v2(115,1) v2(116,37) v2(116,35) v2(116.25,47.5) v2(117,99) v2(117,5) v2(117,3) v2(117,1) v2(117.5,42.75) v2(118.75,52.25) v2(119,99) v2(119,5) v2(119,3) v2(119,1) v2(119.75,47.5) v2(120.75,43) v2(121,99) v2(121,5) v2(121,3) v2(121,1) v2(122,52.25) v2(123,99) v2(123,17) v2(123,15) v2(123,13) v2(123,11) v2(123,5) v2(123,3) v2(123,1) v2(125,99) v2(125,17) v2(125,15) v2(125,13) v2(125,11) v2(125,5) v2(125,3) v2(125,1) v2(127,99) v2(127,17) v2(127,15) v2(127,13) v2(127,11) v2(127,5) v2(127,3) v2(127,1) v2(129,99) v2(129,17) v2(129,15) v2(129,13) v2(129,11) v2(129,5) v2(129,3) v2(129,1) v2(131,99) v2(131,5) v2(131,3) v2(131,1) v2(133,99) v2(133,5) v2(133,3) v2(133,1) v2(133.25,70.62) v2(133.25,70) v2(133.75,68.62) v2(133.75,68) v2(135,99) v2(135,9) v2(135,7) v2(135,5) v2(135,3) v2(135,1) v2(135.62,76.5) v2(136.38,76.5) v2(137,99) v2(137,9) v2(137,7) v2(137,5) v2(137,3) v2(137,1) v2(137.12,76.5) v2(139,99) v2(139,9) v2(139,7) v2(139,5) v2(139,3) v2(139,1) v2(139.38,67.5) v2(139.62,69.12) v2(140.88,70.25) v2(141,99) v2(141,9) v2(141,7) v2(141,5) v2(141,3) v2(141,1) v2(141.25,60.5) v2(141.38,57.88) v2(142.5,71.25) v2(143,99) v2(143,86.12) v2(143,85.25) v2(143,84.38) v2(143,17) v2(143,15) v2(143,13) v2(143,11) v2(143,9) v2(143,7) v2(143,5) v2(143,3) v2(143,1) v2(143.25,71.25) v2(143.5,89.12) v2(143.5,88.5) v2(143.5,87.88) v2(143.5,85.75) v2(143.5,84.88) v2(143.5,82.62) v2(143.5,81.88) v2(143.5,81.12) v2(143.75,61.25) v2(143.88,84.38) v2(144,86.12) v2(144,85.25) v2(144.5,60.38) v2(144.5,57.88) v2(145,99) v2(145,17) v2(145,15) v2(145,13) v2(145,11) v2(145,9) v2(145,7) v2(145,5) v2(145,3) v2(145,1) v2(146.38,58) v2(147,99) v2(147,17) v2(147,15) v2(147,13) v2(147,11) v2(147,9) v2(147,7) v2(147,5) v2(147,3) v2(147,1) v2(147.75,38) v2(148,90.5) v2(148.5,89.6) v2(149,99) v2(149,17) v2(149,15) v2(149,13) v2(149,11) v2(149,9) v2(149,7) v2(149,5) v2(149,3) v2(149,1) v2(149.25,90.5) v2(149.75,58.25) v2(150.62,58.25) v2(151,99) v2(151,17) v2(151,15) v2(151,13) v2(151,11) v2(151,9) v2(151,7) v2(151,5) v2(151,3) v2(151,1) v2(151.75,38) v2(152.75,84.5) v2(153,99) v2(153,29) v2(153,17) v2(153,15) v2(153,13) v2(153,11) v2(153,9) v2(153,7) v2(153,5) v2(153,3) v2(153,1) v2(153.5,24.25) v2(153.75,33.5) v2(154.25,42.25) v2(155,99) v2(155,17) v2(155,15) v2(155,13) v2(155,11) v2(155,9) v2(155,7) v2(155,5) v2(155,3) v2(155,1) v2(155.5,38) v2(155.88,51) v2(156.5,24.5) v2(156.75,51) v2(157,99) v2(157,17) v2(157,15) v2(157,13) v2(157,11) v2(157,9) v2(157,7) v2(157,5) v2(157,3) v2(157,1) v2(157.5,29.25) v2(157.62,51) v2(158.25,33.75) v2(158.75,42.25) v2(159,99) v2(159,63) v2(159,61) v2(159,59) v2(159,57) v2(159,55) v2(159,53) v2(159,17) v2(159,15) v2(159,13) v2(159,11) v2(159,9) v2(159,7) v2(159,5) v2(159,3) v2(159,1) v2(160,38) v2(160.5,49.5) v2(161,99) v2(161,63) v2(161,61) v2(161,59) v2(161,57) v2(161,55) v2(161,53) v2(161,17) v2(161,15) v2(161,13) v2(161,11) v2(161,9) v2(161,7) v2(161,5) v2(161,3) v2(161,1) v2(161.5,49.5) v2(163,99) v2(163,63) v2(163,61) v2(163,59) v2(163,57) v2(163,55) v2(163,53) v2(163,17) v2(163,15) v2(163,13) v2(163,11) v2(163,9) v2(163,7) v2(163,5) v2(163,3) v2(163,1) v2(164.88,87.75) v2(164.88,87.12) v2(164.88,86.38) v2(164.88,83.88) v2(164.88,83.12) v2(164.88,82.38) v2(165,99) v2(165,63) v2(165,61) v2(165,59) v2(165,57) v2(165,55) v2(165,53) v2(165,17) v2(165,15) v2(165,13) v2(165,11) v2(165,9) v2(165,7) v2(165,5) v2(165,3) v2(165,1) v2(166,48.12) v2(166,46.25) v2(166,44.38) v2(167,99) v2(167,79) v2(167,77) v2(167,75) v2(167,73) v2(167,71) v2(167,69) v2(167,67) v2(167,65) v2(167,63) v2(167,61) v2(167,59) v2(167,57) v2(167,55) v2(167,53) v2(167,1) v2(168.88,85.25) v2(169,99) v2(169,79) v2(169,77) v2(169,75) v2(169,73) v2(169,71) v2(169,69) v2(169,67) v2(169,65) v2(169,63) v2(169,61) v2(169,59) v2(169,57) v2(169,55) v2(169,53) v2(169,1) v2(169.75,85.25) v2(170.62,85.25) v2(170.62,10.38) v2(170.62,9.38) v2(170.75,12.62) v2(170.75,11.62) v2(171,99) v2(171,79) v2(171,77) v2(171,75) v2(171,73) v2(171,71) v2(171,69) v2(171,67) v2(171,65) v2(171,63) v2(171,61) v2(171,59) v2(171,57) v2(171,1) v2(173,99) v2(173,79) v2(173,77) v2(173,75) v2(173,73) v2(173,71) v2(173,69) v2(173,67) v2(173,65) v2(173,63) v2(173,61) v2(173,59) v2(173,57) v2(173,1) v2(174,91.5) v2(174,90.5) v2(174.5,13.5) v2(175,99) v2(175,1) v2(176.25,90.5) v2(177,99) v2(177,1) v2(179,99) v2(179,1) v2(179.62,89.25) v2(180.38,89.25) v2(181,99) v2(181,1) v2(181.75,88) v2(182.62,88) v2(183,99) v2(183,1) v2(183.5,88) v2(185,99) v2(185,1) v2(187,99) v2(187,1) v2(189,99) v2(189,1) v2(191,99) v2(191,97) v2(191,95) v2(191,93) v2(191,91) v2(191,89) v2(191,87) v2(191,85) v2(191,83) v2(191,81) v2(191,79) v2(191,77) v2(191,75) v2(191,73) v2(191,71) v2(191,69) v2(191,67) v2(191,65) v2(191,63) v2(191,61) v2(191,59) v2(193,99) v2(193,97) v2(193,95) v2(193,93) v2(193,91) v2(193,89) v2(193,87) v2(193,85) v2(193,83) v2(193,81) v2(193,79) v2(193,77) v2(193,75) v2(193,73) v2(193,71) v2(193,69) v2(193,67) v2(193,65) v2(193,63) v2(193,61) v2(193,59) v2(195,99) v2(195,97) v2(195,95) v2(195,93) v2(195,91) v2(195,89) v2(195,87) v2(195,85) v2(195,83) v2(195,81) v2(195,79) v2(195,77) v2(195,75) v2(195,73) v2(195,71) v2(195,69) v2(195,67) v2(195,65) v2(195,63) v2(195,61) v2(195,59) v2(197,99) v2(197,97) v2(197,95) v2(197,93) v2(197,91) v2(197,89) v2(197,87) v2(197,85) v2(197,83) v2(197,81) v2(197,79) v2(197,77) v2(197,75) v2(197,73) v2(197,71) v2(197,69) v2(197,67) v2(197,65) v2(197,63) v2(197,61) v2(197,59) v2(199,99) v2(199,97) v2(199,95) v2(199,93) v2(199,91) v2(199,89) v2(199,87) v2(199,85) v2(199,83) v2(199,81) v2(199,79) v2(199,77) v2(199,75) v2(199,73) v2(199,71) v2(199,69) v2(199,67) v2(199,65) v2(199,63) v2(199,61) v2(199,59) v2(199,57) v2(199,55) v2(199,53) v2(199,51) v2(199,49) v2(199,47) v2(199,45) v2(199,43) v2(199,41) v2(199,39) v2(199,37) v2(199,35) v2(199,33) v2(199,31) v2(199,29) v2(199,27) v2(199,25) v2(199,23) v2(199,21) v2(199,19) v2(199,17) v2(199,15) v2(199,13) v2(199,11) v2(199,9) v2(199,7) v2(199,5) v2(199,3) v2(199,1) v2(199,1) v3(9.5,61.75) v3(9.5,59.75) v3(9.5,57.75) v3(9.5,42.25) v3(9.5,40.25) v3(9.5,38.25) v3(11.4,60.75) v3(11.4,59.75) v3(11.4,58.75) v3(11.4,57.75) v3(11.4,42.25) v3(11.4,41.25) v3(11.4,40.25) v3(11.4,39.25) v3(13.6,60.75) v3(13.6,59.75) v3(13.6,58.75) v3(13.6,57.75) v3(13.6,42.25) v3(13.6,41.25) v3(13.6,40.25) v3(13.6,39.25) v3(15.5,61.75) v3(15.5,59.75) v3(15.5,57.75) v3(15.5,42.25) v3(15.5,40.25) v3(36.75,64.5) v3(36.75,62.5) v3(36.75,60.5) v3(36.75,39.5) v3(36.75,37.5) v3(36.75,35.5) v3(38.65,63.5) v3(38.65,62.5) v3(38.65,61.5) v3(38.65,60.5) v3(38.65,39.5) v3(38.65,38.5) v3(38.65,37.5) v3(38.65,36.5) v3(40.85,63.5) v3(40.85,62.5) v3(40.85,61.5) v3(40.85,60.5) v3(40.85,39.5) v3(40.85,38.5) v3(40.85,37.5) v3(40.85,36.5) v3(42.75,64.5) v3(42.75,62.5) v3(42.75,60.5) v3(42.75,39.5) v3(42.75,37.5) v3(42.75,35.5) v4(11,62.25) v4(11,37.75) v4(14,62.25) v4(14,37.75) v4(38.25,65) v4(38.25,35) v4(41.25,65) v4(41.25,35)
A: length 22.9
  TOP w0.5: A.1 108.48,21.77 U9.5 99.98,21.77 99,22.75 99,23.75 98.5,24.25 98.07,24.25 98.01,24.31 U9.8
B: length 13.5
  TOP w0.25: B.1 113.59,23 113.55,23.04 U9.6
CONVST: length 4.6
  TOP w0.25: R24.1 173.5,22.25 173,22.75 173,24.25 173.25,24.5 R23.1
CONVSTB: length 81.5
  TOP w0.25: U2.6 106.5,49.25 115.25,40.5 T6.1 139.75,26.75 R25.2
CSB: length 84
  TOP w0.25: 172.25,31.25 140,31.25 T7.1 111.14,45.25 106.64,49.75 U2.7 ; 172.25,31.25 R21.2 ; 172.25,31.25 172.25,29.5 172.75,29 R19.2
GPIO1: length 88.1
  TOP w0.25: J4.78 187.5,21 187,20.5 168.25,20.5 167.5,19.75 140.5,19.75 128.5,7.75 GPIO1.1 D2.C
GPIO2: length 97.8
  TOP w0.25: v2(188.75,19.75) v2(169.25,19.75) ; v2(169.25,22) 130.5,22 122,30.5 GPIO2.1 113.59,30.5 113.34,30.75 D3.C ; J4.44 v2(198.65,20.4)
  BOTTOM w0.25: v2(169.25,19.75) v2(169.25,22) ; v2(188.75,19.75) 189.4,20.4 v2(198.65,20.4)
RF1: length 11.2
  TOP w0.356: RF1.1 39.75,52.14 U10.7 39.75,51.25
RF2: length 11.3
  TOP w0.356: RF2.1 39.75,47.86 U10.14 39.75,48.81
RF_TRUE_CAL: length 19.5
  TOP w0.356: J5.1 J3.1
RFIN: length 10.5
  TOP w0.356: 41.19,50.25 U10.3 42.14,50.25 U1.5
SCLK: length 82.2
  TOP w0.25: 172.5,35.75 172.5,33.75 172.75,33.5 R17.2 ; 172.5,35.75 140.25,35.75 T8.1 107.03,50 106.78,50.25 U2.8 ; 172.5,35.75 R20.2
SDO: length 84
  TOP w0.25: 172.49,40.25 R18.2 ; 172.49,40.25 140.5,40.25 T9.1 116.5,54.75 112.5,50.75 U2.9 ; 172.49,40.25 172.49,38.01 172.5,38 R22.2
UNNAMED_3_AD7091RV2_I14_REFOUT: length 17.3
  TOP w0.25: C11.1 96.15,50.75 U2.2
  TOP w0.5: C11.1 93.15,51.65 C12.1 91.55,51.8 88.25,55.09 T2.1
UNNAMED_3_AD7091RV2_I14_VIN: length 18.2
  TOP w0.25: C37.1 90.36,50.5 91.25,50.5 91.5,50.25 U2.3
  TOP w0.5: R31.2 T3.1 85.28,50.25 85.38,50.35 R40.1 89.36,50.35 89.39,50.38 C37.1
UNNAMED_3_CAP_I29_N1: length 9.9
  TOP w0.25: 95,47 95,48.75 96,49.75 U2.4
  TOP w0.5: C14.1 95,47 93,45 T4.1
UNNAMED_4_ADM660_I4_CAP: length 2.8
  TOP w0.5: U11.4 141.4,56.59 C36.N
UNNAMED_4_ADM660_I4_CAP_1: length 2.7
  TOP w0.5: C36.P 141.13,59.13 U11.2
UNNAMED_4_ADM7170_I67_VOUT1: length 0.5
  TOP w0.25: U8.2 U8.1
UNNAMED_4_ADP2301_I57_EN: length 14.7
  TOP w0.5: v2(162,88.75) 162,87.3 R14.1 ; U7.4 v2(172.69,92.44)
  BOTTOM w0.5: v2(162,88.75) 165.69,92.44 v2(172.69,92.44)
UNNAMED_4_ADP3303_I47_ERRN: length 12.6
  TOP w0.5: v2(137.75,70) 138.63,70 R12.1 ; U6.6 v2(129.63,74.39)
  BOTTOM w0.5: v2(129.63,74.39) 133.37,74.39 v2(137.75,70)
UNNAMED_5_CN120PV4_I55_EEPROMA0: length 27.2
  TOP w0.25: R28.1 174.48,9.75 174.53,9.7 U5.1 176.02,8.71 176,8.69 176,8.25 176.5,7.75 190.12,7.75 195.58,13.2 J4.56
UNNAMED_5_CN120PV4_I55_GPIO0: length 24.8
  TOP w0.25: v2(188,22.75) 187.57,22.75 187.24,23.08 183.05,23.08 182.21,22.25 177.75,22.25 R24.2 ; J4.43 v2(198.25,21)
  BOTTOM w0.25: v2(198.25,21) 189.75,21 v2(188,22.75)
UNNAMED_5_CN120PV4_I55_SCL0: length 17.9
  TOP w0.25: v2(177.25,16) 177.25,15.36 177.33,15.29 U5.6 ; J4.79 v2(185.85,21.6)
  BOTTOM w0.25: v2(185.85,21.6) 182.85,21.6 v2(177.25,16)
UNNAMED_5_CN120PV4_I55_SDA0: length 18.1
  TOP w0.25: v2(178,15.75) 178,14.32 U5.5 ; J4.80 188.27,22.2 188.24,22.17 187.76,22.17 187.73,22.2 187.3,22.2 v2(187,22.5)
  BOTTOM w0.25: v2(187,22.5) 187,21.5 186.25,20.75 183.5,20.75 183.25,20.5 182.75,20.5 v2(178,15.75)
UNNAMED_5_CN120PV4_I55_SPICLK: length 22.8
  TOP w0.25: J4.82 187.56,23.4 187.43,23.54 182.86,23.54 182.74,23.42 181.83,23.42 181.25,24 181.25,24.25 v2(179.75,25.75) ; v2(177.75,33.5) R17.1
  BOTTOM w0.25: v2(179.75,25.75) 179.75,31.5 v2(177.75,33.5)
UNNAMED_5_CN120PV4_I55_SPIMISO: length 30.9
  TOP w0.25: J4.83 v2(182.5,24) ; v2(181.75,40.25) R18.1
  BOTTOM w0.25: v2(181.75,40.25) 182.5,39.5 v2(182.5,24)
UNNAMED_5_CN120PV4_I55_SPISELA: length 16.6
  TOP w0.25: J4.85 181.8,25.2 178,29 R19.1
UNNAMED_5_CN120PV4_I55_SPORTDR0: length 20.9
  TOP w0.25: J4.91 184.45,28.8 v2(178.75,34.5) ; v2(178.75,38) R22.1
  BOTTOM w0.25: v2(178.75,34.5) v2(178.75,38)
UNNAMED_5_CN120PV4_I55_SPORTRFS: length 18.6
  TOP w0.25: 189.5,28.2 189.5,27.6 J4.89 ; 189.5,28.2 J4.90 ; 189.5,28.2 181.3,28.2 178.25,31.25 R21.1
UNNAMED_5_CN120PV4_I55_SPORTRSC: length 24.5
  TOP w0.25: R20.1 179.25,35.75 185.25,29.75 v2(187.65,29.75) 188.88,29.75 189.23,29.4 J4.92 ; J4.87 v2(187.65,26.4)
  BOTTOM w0.25: v2(187.65,26.4) v2(187.65,29.75)
UNNAMED_5_CN120PV4_I55_TMRA: length 30.5
  TOP w0.25: J4.48 v2(198.25,18) ; v2(177.5,18.25) 178.5,17.25 v2(188.25,17.25) ; v2(177.5,24.5) R23.2
  BOTTOM w0.25: v2(188.25,17.25) 189,18 v2(198.25,18) ; v2(177.5,18.25) v2(177.5,24.5)
UNNAMED_5_CN120PV4_I55_TMRB: length 22.7
  TOP w0.25: v2(178.5,19) 179.5,18 J4.73 ; R25.1 177.5,26.75 v2(178.5,25.75) 178.55,25.7
  BOTTOM w0.25: v2(178.5,19) v2(178.5,25.75)
UNNAMED_5_IC24FC256_I33_A1: length 9.1
  TOP w0.25: U5.2 176.67,10.83 175.5,12 R27.1 173.6,12.93 173.5,13.03 173.5,13.25 173.25,13.5 172.5,13.5 171.9,14.1 R26.2
UNNAMED_8_7404_I38_IN: length 75.9
  TOP w0.25: U10.11 38.07,49.75 37.99,49.67 v2(37.33,49.67)
  TOP w0.5: U9.12 94.75,19.23 94.25,19.73 94.25,20 v2(94.75,20.5) U9.11
  BOTTOM w0.25: v2(94.75,20.5) 70.5,44.75 42.25,44.75 v2(37.33,49.67)
UNNAMED_8_7404_I38_OUTN: length 71.3
  TOP w0.25: v2(95,21.75) 96.44,21.75 U9.10 ; U10.10 v2(37.75,50.25)
  BOTTOM w0.25: v2(95,21.75) 71.25,45.5 42.5,45.5 v2(37.75,50.25)
UNNAMED_8_7404_I39_IN: length 15.5
  TOP w0.5: D2.A 98.34,9.16 98.4,9.21 R30.1 96,12.25 94,14.25 94,17.25 94.71,17.96 U9.13
UNNAMED_8_7404_I65_IN: length 13.4
  TOP w0.5: U9.9 94.79,23.04 93.75,24.08 93.75,25 95.75,27 R36.1 98.4,29.15 98.59,29.34 D3.A
UNNAMED_8_ADL6010_I98_VOUT: length 5.7
  TOP w0.3: U1.2 54.63,50.25 54.74,50.13 C3.1
  TOP w0.5: R1.1 58.47,50.25 58.35,50.13 C3.1
V_IN: length 0.5
  TOP w0.25: U8.7 U8.8
V_OUT: length 17.5
  TOP w0.5: R31.1 V_OUT.1 R1.2
VDET: length 1.2
  TOP w0.5: v1(153,79) v1(153,77.75)
  vias: v1(149,65.75) v1(149,64.75) v1(150.25,65.75) v1(150.25,64.75) v1(151.5,65.75) v1(151.5,64.75) v1(154,79) v1(154,77.75) v1(155,79) v1(155,77.75)
VIO_CONNECTOR: length 40.7
  TOP w0.3: U5.3 177.33,11.67 176,13 176,14.28 U5.8 175.8,14.3
  TOP w0.8: R26.1 174.75,15.25 175.7,14.3 175.8,14.3
  TOP w1: R26.1 v2(173.6,17.15)
  BOTTOM w1: v2(173.6,17.15) 173.6,42.15 v2(169.5,46.25)
VNEG:
  vias: v1(118.75,27) v1(118.75,25.75) v1(118.75,24.25) v1(120.25,27) v1(120.25,25.75) v1(120.25,24.25)

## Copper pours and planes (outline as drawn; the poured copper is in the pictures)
AGND on TOP (solid shape): 9.38,57.88 9.25,57.75 6.12,57.75 6,57.88 6,61.25 9.38,61.25
AGND on TOP (solid shape): 9.5,38.88 9.38,38.75 6.25,38.75 6.12,38.88 6.12,42.25 9.5,42.25
AGND on TOP (solid shape): 18.88,57.88 18.75,57.75 15.62,57.75 15.5,57.88 15.5,61.25 18.88,61.25
AGND on TOP (solid shape): 18.88,39 18.75,38.88 15.62,38.88 15.5,39 15.5,42.38 18.88,42.38
AGND on TOP (solid shape): 36.62,60.62 36.5,60.5 33.38,60.5 33.25,60.62 33.25,64 36.62,64
AGND on TOP (solid shape): 36.75,36.12 36.62,36 33.5,36 33.38,36.12 33.38,39.5 36.75,39.5
AGND on TOP (solid shape): 46,36.25 45.88,36.12 42.75,36.12 42.62,36.25 42.62,39.62 46,39.62
AGND on TOP (solid shape): 46.12,60.5 46,60.38 42.88,60.38 42.75,60.5 42.75,63.88 46.12,63.88
AGND on TOP (solid shape): 53.12,49.42 51.73,49.42 51.73,49.78 52.25,49.78 52.25,50.72 51.73,50.72 51.73,51.08 53.12,51.08
AGND on BOTTOM (solid shape): 9.62,61.25 9.62,58 9.12,57.5 6.12,57.5 6,57.62 6,61.38 9.5,61.38
AGND on BOTTOM (solid shape): 9.62,42.25 9.62,39 9.12,38.5 6.12,38.5 6,38.62 6,42.38 9.5,42.38
AGND on BOTTOM (solid shape): 19,61.25 19,58 18.5,57.5 15.5,57.5 15.38,57.62 15.38,61.38 18.88,61.38
AGND on BOTTOM (solid shape): 19.12,42.38 19.12,39.12 18.62,38.62 15.62,38.62 15.5,38.75 15.5,42.5 19,42.5
AGND on BOTTOM (solid shape): 36.88,39.62 36.88,36.38 36.38,35.88 33.38,35.88 33.25,36 33.25,39.75 36.75,39.75
AGND on BOTTOM (solid shape): 37,64.12 37,60.88 36.5,60.38 33.5,60.38 33.38,60.5 33.38,64.25 36.88,64.25
AGND on BOTTOM (solid shape): 46.12,64 46.12,60.75 45.62,60.25 42.62,60.25 42.5,60.38 42.5,64.12 46,64.12
AGND on BOTTOM (solid shape): 46.38,39.5 46.38,36.25 45.88,35.75 42.88,35.75 42.75,35.88 42.75,39.62 46.25,39.62
AGND on TOP: 149.5,91.5 143.25,91.5 142.75,91 142.75,85.75 141.5,85.75 141.5,85.25 142.75,85.25 142.75,83.75 142.5,83.5 141.75,83.5 141.75,79.5 145,79.5 145.25,79.75 145.25,83.25 144.25,84.25 144.25,86.5 145.25,87.5 145.25,89.5 145.75,90 147.25,90 148,89.25 149.5,89.25
AGND on TOP: 137.75,77 133.25,77 132.75,76.5 132.75,70.75 132.25,70.25 132,70.25 132,64.75 142,64.75 142,67.5 141.25,68.25 141.25,69.75 142.25,70.75 146.25,70.75 146.25,71.75 141.25,71.75 139.75,70.25 139.75,69.5 139.25,69 136.25,69 134.75,70.5 134.75,75 135,75.25 137.75,75.25
AGND on TOP, BOTTOM, L2-GND, L3-GND: 199.5,99.5 70.5,99.5 70.5,64.5 47.5,64.5 47.5,65 32,65 32,64.5 25.5,64.5 25.5,61.75 20.5,61.75 20.5,62.25 4.25,62.25 4.25,61.75 0.5,61.75 0.5,38.25 4.5,38.25 4.5,37.75 20.75,37.75 20.75,38.25 25.5,38.25 25.5,35.5 31.75,35.5 31.75,35 47.75,35 47.75,35.5 70.5,35.5 70.5,0.5 199.5,0.5
AVDD on TOP: 142,69.75 143.75,69.75 144,70 146.5,70 146.5,61.5 144.75,61.5 144,62.25 102.75,62.25 98.25,57.75 98.25,51 97,51 96.75,51.25 96.75,57.5 95.75,58.5 95.75,61.25 98.75,64.25 142.25,64.25 142.75,64.75 142.75,67.75 142,68.5
UNNAMED_4_ADM660_I4_OUT on TOP: 147,57 151.25,57 151.25,54.25 147,54.25
UNNAMED_4_ADM660_I4_V on TOP: 147,63.5 147,60 149.5,60 149.5,63.5
UNNAMED_4_ADM7170_I67_EN on TOP: 134.5,87.75 136.75,87.75 138,86.5 142.25,86.5 142.25,86 134.75,86 134.5,86.25
UNNAMED_4_ADM7170_I67_SENSE on TOP: 144.75,85.75 145.75,85.75 147.75,87.75 147.75,88.5 149.75,88.5 150.5,89.25 152,89.25 152,84.25 151.75,84 150.5,84 149.25,85.25 144.75,85.25
UNNAMED_4_ADM7170_I67_SS on TOP: 147.25,89.5 146,89.5 145.75,89.25 145.75,87.25 145.5,87 145.25,87 144.5,86.25 144.5,86 145.5,86 147.25,87.75
UNNAMED_4_ADM7170_I67_VOUT1 on TOP: 144.75,85 147.5,85 147.75,84.75 149.25,84.75 150.5,83.5 152.5,83.5 153.5,84.5 155.25,84.5 155.25,81.5 149.25,81.5 148.75,81 146,81 145.75,81.25 145.75,83.25 144.75,84.25
